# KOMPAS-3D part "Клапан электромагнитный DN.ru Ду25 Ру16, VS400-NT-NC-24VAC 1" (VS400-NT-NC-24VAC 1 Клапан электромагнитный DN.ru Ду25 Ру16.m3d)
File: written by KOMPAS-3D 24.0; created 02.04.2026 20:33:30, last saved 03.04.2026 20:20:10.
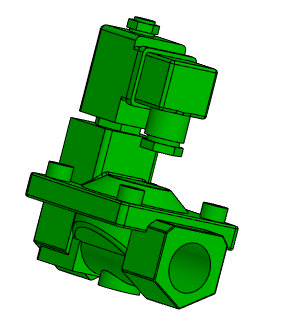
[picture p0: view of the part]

Document properties: Автор: artio; Полное имя файла: C:\Users\artio\OneDrive\Рабочий стол\Клапан электромагнитный DN.ru\VS400-NT-NC\VS400-NT-NC-24VAC 1 Клапан электромагнитный DN.ru Ду25 Ру16.m3d

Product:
- Body: Тело 1  | qty 1
    Масса: 1.76797
- Part/product: Клапан электромагнитный DN.ru Ду25 Ру16  | designation VS400-NT-NC-24VAC 1
    Масса: 1.524
    Раздел спецификации: Прочие изделия
    Примечание: D130-05494
    additional columns: ef56311e-7521-43dc-8291-0e6108b3d81d; VS400-ET-NC-220VAC 1; artio; c; Шероховатость не задана; Да

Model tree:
1. Операция без истории:1

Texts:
  VS400-NT-NC-24VAC 1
